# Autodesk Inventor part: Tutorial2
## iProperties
Created: 2001-11
Part Number: Tutorial2
Document SubType Name: Modeling
Designer: Renu Muthoo
Control State: 0
Master: False
Checked Out: False
Shininess: 77.0
Length Units: 11269
Angle Units: 11279
Time Units: 11290
Mass Units: 11283
Length Display Precision: 3
Angle Display Precision: 2
Density: 0.0
Volumn: 0.0
Area: 0.0
PropertySet Name: Model Information
Author: Renu Muthoo
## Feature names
1. Extrusion1
2. Extrusion2
3. Extrusion3
4. Extrusion4
5. Extrusion5
